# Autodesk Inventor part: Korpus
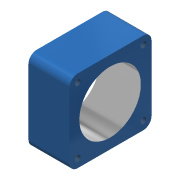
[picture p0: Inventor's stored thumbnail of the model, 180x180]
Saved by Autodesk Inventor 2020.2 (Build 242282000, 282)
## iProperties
Created: 2005-10
Part Number: Korpus
Document SubType Name: Modeling
Designer: F.Stasiak
Density: 1 g/cm^3
Material: Ogólny
Appearance: Cyjan
Manager: www.cadconsulting.pl
Company: Fabian Stasiak CAD Consulting
Author: F.Stasiak
Subject: Zbiór ćwiczeń. Autodesk Inventor 2020. Kurs podstawowy
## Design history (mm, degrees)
sketch "Szkic1"
  geometry: L1 (-25, 50)-(25, 50); L2 (25, 50)-(25, -50); L3 (25, -50)-(-25, -50); L4 (-25, -50)-(-25, 50); L5 (0, 50)-(0, -50); 2 further points
  constraints: 10 end point, 3 midpoint, 2 parallel, 1 coincident, 1 horizontal, 1 perpendicular, 1 other
  dimensions: "d0" = 50 distance of L2.end L3.end; "d1" = 100 distance of L3.end L1.start
extrude "Wyciągnięcie proste1" new body sketch "Szkic1" stored distance "d2" = 100; taper "d3" = 0 deg
fillet "Zaokrąglenie1" dims "d4" = 10
sketch "Szkic2"
  geometry: L1 (10, 90)-(90, 90) reference; L2 (0, 80)-(0, 0) reference; L3 (10, -10)-(90, -10) reference; L4 (100, 0)-(100, 80) reference; A1 r 10 centre (90, 80) between (100, 80) and (90, 90) reference; A2 r 10 centre (10, 80) between (10, 90) and (0, 80) reference; A3 r 10 centre (10, 0) between (0, 0) and (10, -10) reference; A4 r 10 centre (90, 0) between (90, -10) and (100, 0) reference
hole "Otwór1" sketch "Szkic2" at (10, 80), (90, 80), (90, 0), (10, 0) diameter "d5" = 6.917; stored, may be unused: countersink angle "d9" = 90 deg, drill point angle "d11" = 118 deg; dims "d6" = 6, "d7" = 4, "d8" = 2, "d10" = 8
sketch "Szkic3"
  geometry: L1 (10, 0)-(90, 80); C1 r 3.458 at (10, 80) reference; C2 r 3.458 at (90, 0) reference; C3 r 37.5 at (50, 39.512); C4 r 3.458 at (10, 0) reference; C5 r 3.458 at (90, 80) reference
  constraints: 2 end point, 1 centre point
  dimensions: "d12" = 75 diameter of C3
extrude "Wyciągnięcie proste2" cut sketch "Szkic3" extent not by distance; stored distance "d13" = 100; taper "d14" = 0 deg
node "Bryła1"
node "Korpusy bryłowe"
node "Korpusy powierzchniowe"
node "Pętla rzutowana1"
